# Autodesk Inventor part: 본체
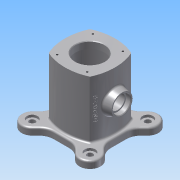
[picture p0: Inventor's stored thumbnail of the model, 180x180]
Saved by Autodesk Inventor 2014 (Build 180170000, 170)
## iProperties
Created: 2016-05
Part Number: 본체
Material: 알루미늄 6061
Document SubType Name: Modeling
Designer: 703-04
Density: 2.71 g/cm^3
Appearance: 알루미늄 - 평지
Mass: 1104.96 g
Surface Area: 864.807 cm^2
Volume: 407.733 cm^3
Author: 703-04
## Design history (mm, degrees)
sketch "스케치1"
  geometry: L1 (0, 70)-(0, -70); L2 (-49.497, 49.497)-(49.497, -49.497); L3 (49.497, -49.497)-(-49.497, 49.497); L4 (-56.322, 30.866)-(-62.225, 36.77); L5 (-36.77, 62.225)-(-30.866, 56.322); L6 (49.497, 49.497)-(-49.497, -49.497); L7 (-49.497, -49.497)-(49.497, 49.497); L8 (56.322, 30.866)-(62.225, 36.77); L9 (-56.322, -30.866)-(-62.225, -36.77); L10 (-49, 13.189)-(-49, -13.189); L11 (-49, -49)-(49, 49); L12 (48.999, -48.503)-(-49, 48.504); L13 (49, 13.189)-(49, -13.189); L14 (56.322, -30.866)-(62.225, -36.77); L15 (13.189, 49)-(-13.189, 49); L16 (-49, -49)-(49, 49); L17 (49, -49)-(-49, 49); L18 (36.77, 62.225)-(30.866, 56.322); L19 (-70, 0)-(70, 0); L20 (-36.77, -62.225)-(-30.866, -56.322); L21 (13.189, -49)-(-13.189, -49); L22 (36.77, -62.225)-(30.866, -56.322); A1 r 18 centre (49.497, -49.497) between (36.77, -62.225) and (62.225, -36.77); A2 r 18 centre (-49.497, 49.497) between (-36.77, 62.225) and (-62.225, 36.77); A3 r 18 centre (-49.497, -49.497) between (-62.225, -36.77) and (-36.77, -62.225); A4 r 18 centre (49.497, 49.497) between (62.225, 36.77) and (36.77, 62.225); A5 r 25 centre (-74, 13.189) between (-49, 13.189) and (-56.322, 30.866); A6 r 25 centre (-74, -13.189) between (-56.322, -30.866) and (-49, -13.189); A7 r 25 centre (-13.189, 74) between (-30.866, 56.322) and (-13.189, 49); A8 r 25 centre (74, 13.189) between (56.322, 30.866) and (49, 13.189); A9 r 25 centre (74, -13.189) between (49, -13.189) and (56.322, -30.866); A10 r 25 centre (13.189, 74) between (13.189, 49) and (30.866, 56.322); A11 r 25 centre (-13.189, -74) between (-13.189, -49) and (-30.866, -56.322); A12 r 25 centre (13.189, -74) between (30.866, -56.322) and (13.189, -49); 5 further points
  constraints: 48 end point, 24 point on circle, 14 symmetric about line, 14 tangent, 12 centre point, 10 midpoint, 8 point on line, 3 parallel, 1 coincident, 1 collinear, 1 equal radius, 1 perpendicular, 1 vertical, 1 vertical alignment, 5 other
  dimensions: "d1" = 45 deg angle of L1 L2; "d3" = 18 radius of A2; "d4" = 18 radius of A4; "d9" = 98 distance of L11.start L12.start; "d11" = 25 radius of A5; "d12" = 25 radius of A7; "d15" = 98 vertical distance of L6.start L12.start
extrude "돌출3" new body sketch "스케치1" distance "d16" = 12; taper "d17" = 0 deg
sketch "스케치2"
  geometry: A1 r 18 centre (49.497, -49.497) between (36.77, -62.225) and (62.225, -36.77) reference; A2 r 18 centre (49.497, 49.497) between (62.225, 36.77) and (36.77, 62.225) reference; A3 r 18 centre (-49.497, 49.497) between (-36.77, 62.225) and (-62.225, 36.77) reference; A4 r 18 centre (-49.497, -49.497) between (-62.225, -36.77) and (-36.77, -62.225) reference; 5 further points
  constraints: 4 coincident
hole "구멍1" sketch "스케치2" at (-49.497, 49.497), (49.497, 49.497), (49.497, -49.497), (-49.497, -49.497) diameter "d19" = 10; stored, may be unused: countersink angle "d23" = 90 deg, drill point angle "d25" = 118 deg; dims "d20" = 6, "d21" = 18, "d22" = 4, "d24" = 8
sketch "스케치3"
  geometry: L1 (-35.355, 35.355)-(35.355, 35.355); L2 (35.355, 35.355)-(35.355, -35.355); L3 (35.355, -35.355)-(-35.355, -35.355); L4 (-35.355, -35.355)-(-35.355, 35.355); L5 (-35.355, 35.355)-(35.355, -35.355); L6 (35.355, 35.355)-(-35.355, -35.355); L7 (43, 25.339)-(43, -26.671); L8 (-43, 22.756)-(-43, -22.756); L9 (-36.801, 43)-(36.801, 43); L10 (-36.801, -43)-(36.801, -43); A1 r 85.579 centre (42.579, 0) between (-35.355, 35.355) and (-35.355, -35.355); A2 r 85.579 centre (-42.579, 0) between (35.355, -35.355) and (35.355, 35.355); A3 r 85.579 centre (0, -42.579) between (35.355, 35.355) and (-35.355, 35.355); A4 r 85.579 centre (0, 42.579) between (-35.355, -35.355) and (35.355, -35.355); 10 further points
  constraints: 20 end point, 10 point on circle, 5 midpoint, 5 parallel, 4 centre point, 3 equal radius, 2 coincident, 2 perpendicular, 1 horizontal
  dimensions: "d51" = 100 distance of L1.end L3.end; "d58" = 43 distance from line of point (0, 0) L8; "d59" = 43 distance from line of L7 point (0, 0); "d60" = 43 distance from line of L9 point (0, 0); "d61" = 43 distance from line of point (0, 0) L10
extrude "돌출4" join sketch "스케치3" distance "d42" = 98; taper "d43" = 0 deg
sketch "스케치6"
  geometry: C1 r 25 at (0, 0); 1 further point
  constraints: 1 centre point, 1 coincident
  dimensions: "d62" = 50 diameter of C1
extrude "돌출6" cut sketch "스케치6" stored distance "d63" = 98; taper "d64" = 0 deg
node "작업 평면2"
sketch "스케치7"
  geometry: C1 r 35 at (0, 0); 1 further point
  constraints: 1 centre point, 1 coincident
  dimensions: "d66" = 70 diameter of C1
extrude "돌출7" cut sketch "스케치7" stored distance "d67" = 86; taper "d68" = 0 deg
node "작업 평면3"
sketch "스케치10"
  geometry: C1 r 20 at (0, 61); 1 further point
  constraints: 1 centre point, 1 vertical alignment
  dimensions: "d86" = 40 diameter of C1; "d87" = 61 distance of point (0, 0) C1.centre
extrude "돌출8" join sketch "스케치10" stored distance "d88" = 86; taper "d89" = 0 deg
sketch "스케치11"
  geometry: C1 r 20 at (0, 0) reference; 1 further point
hole "구멍4" sketch "스케치11" at (0, 0) diameter "d90" = 25; stored, may be unused: countersink angle "d94" = 90 deg, drill point angle "d96" = 118 deg; dims "d91" = 7, "d92" = 30, "d93" = 8, "d95" = 10
node "작업 평면4"
feature "면 기울기1" dims angle "d98" = 10 deg
node "작업 평면5"
sketch "스케치13"
  geometry: L1 (35.355, 110)-(-35.355, 110) reference; L2 (0, 0)-(0, 124.644); 1 further point
  constraints: 2 end point, 1 perpendicular, 1 other
  dimensions: "d101" = 29 distance from line of point (-29, 61) L2; "d111" = 49 distance from line of L1 point (-29, 61)
feature "엠보싱1" sketch "스케치13" dims "d102" = 0.5, "d103" = 0
fillet "모깎기1" dims "d104" = 3
fillet "모깎기2" dims "d105" = 3
fillet "모깎기3" dims "d106" = 3
fillet "모깎기4" dims "d107" = 3
chamfer "모따기1" distance "d108" = 1; stored, may be unused: second distance "d109" = 2, angle "d110" = 45 deg
sketch "스케치14" dims "d114" = 80
  geometry: L1 (-49, -13.189)-(-49, 13.189) reference; L2 (-28.284, 28.284)-(28.284, -28.284); L3 (0, 40)-(0, -40); L4 (0, -40)-(0, 40); L5 (28.284, 28.284)-(-28.284, -28.284); C1 r 25 at (0, 0) reference; C2 r 1.621 at (27.919, 28.645) reference; 7 further points
  constraints: 8 end point, 5 coincident, 4 midpoint, 1 parallel, 11 other
  dimensions: "d115" = 45 deg angle of L3 L2; "d116" = 45 deg angle of L5 L3
hole "구멍5" sketch "스케치14" at (-28.284, 28.284), (28.284, 28.284), (28.284, -28.284), (-28.284, -28.284) diameter "d117" = 3.242; stored, may be unused: countersink angle "d121" = 90 deg, drill point angle "d123" = 118 deg; dims "d118" = 7, "d119" = 4, "d120" = 2, "d122" = 10
sketch "스케치15"
  geometry: L1 (0, 40)-(0, -40); L2 (25.712, 30.642)-(-25.712, -30.642); L3 (-25.712, 30.642)-(25.712, -30.642); C1 r 26 at (0, 0) reference; A1 r 40 centre (0, 0) between (0, 40) and (0, -40); 5 further points
  constraints: 6 end point, 5 point on circle, 4 coincident, 2 midpoint, 2 symmetric about line, 1 centre point, 1 vertical
  dimensions: "d124" = 80 diameter of A1; "d125" = 40 deg angle of L2 L1
hole "구멍6" sketch "스케치15" at (-25.712, 30.642), (25.712, 30.642), (-25.712, -30.642), (25.712, -30.642) diameter "d126" = 3.242; stored, may be unused: countersink angle "d130" = 90 deg, drill point angle "d132" = 118 deg; dims "d127" = 7, "d128" = 4, "d129" = 2, "d131" = 10
fillet "모깎기5" dims "d133" = 3
node "솔리드2"
other parameters: "d65" = 55, "d85" = 55, "d97" = 43, "d99" = 43.5
